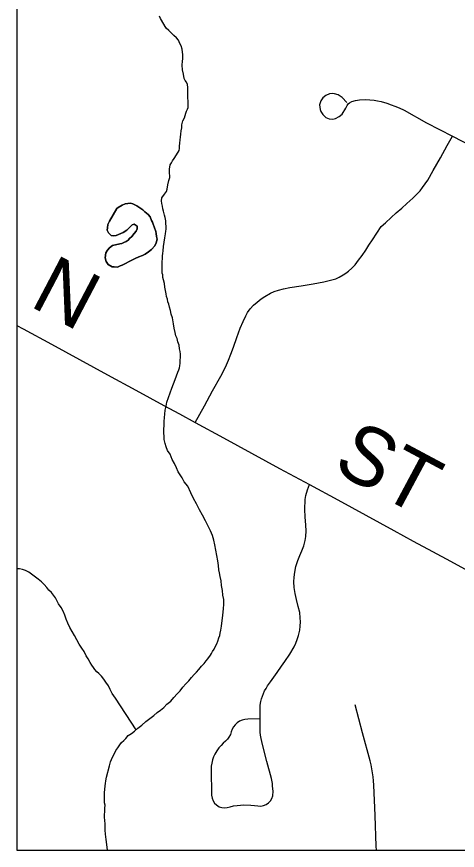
# Model space of a CAD drawing. Extents: x 103424 to 286016, y 38711 to 110967.
# Drawn here: x 103424 to 105694, y 38711 to 43011 of the extents above; entities that cross this region are included whole.
import ezdxf

# ---------------------------------------------------------------- set-up
doc = ezdxf.new("R2010")
doc.units = 0
for name, color, linetype in [('GM_X_Corporation', 7, 'Continuous'), ('GM_X_County_Road', 7, 'Continuous'), ('GM_X_County_Road_Text', 7, 'Continuous'), ('GM_X_Minor_Lake', 7, 'Continuous'), ('GM_X_Minor_River', 7, 'Continuous'), ('GM_X_Township_Road', 7, 'Continuous')]:
    doc.layers.add(name, color=color, linetype=linetype)

msp = doc.modelspace()

# ---------------------------------------------------------------- linework, layer by layer
at = {"layer": 'GM_X_Corporation'}
for points in [[(103423.7, 96534.8), (103423.7, 38711.2), (175679.7, 38711.2), (175679.7, 110967.2), (119699, 110967.2), (119716.9, 106542.5), (119719.8, 106322.8), (119720.8, 106006.3), (119709.7, 99445.7), (119706.4, 99064.2), (119663.9, 96690), (117026.4, 96688.2), (115542.1, 96665), (105081.7, 96574.5)], [(103423.7, 43132.7), (103423.7, 38711.2), (119963.5, 38711.2), (119934.2, 43543), (116952, 43470.9), (108691.3, 43264.4)]]:
    msp.add_lwpolyline(points, close=True, dxfattribs=at)
at = {"layer": 'GM_X_County_Road'}
msp.add_lwpolyline([(103423.7, 41418.7), (103457.3, 41400.5), (103602.3, 41321.6), (103747.3, 41242.7), (103892.3, 41163.9), (104037.3, 41085), (104182.3, 41006.1), (104263.1, 40962.2), (104343.9, 40918.3), (104488.9, 40839.3), (104633.8, 40760.4), (104778.8, 40681.4), (104855.9, 40639.4), (104933, 40597.4), (105077.9, 40518.4), (105222.9, 40439.5), (105367.8, 40360.5), (105467.1, 40306.4), (105566.5, 40252.2), (105658.5, 40202.8), (105750.4, 40153.3)], dxfattribs=at)
at = {"layer": 'GM_X_Minor_Lake'}
for points in [[(103939.2, 42021.1), (103946.5, 42026.4), (103966.4, 42038.9), (103982.5, 42045.2), (103996.6, 42047.4), (104010.7, 42049.7), (104022.8, 42045.9), (104033, 42040), (104043.2, 42036.1), (104063.6, 42022.3), (104073.8, 42014.4), (104084.1, 42004.4), (104100.4, 41990.6), (104110.7, 41978.6), (104119.1, 41960.6), (104123.3, 41950.5), (104127.5, 41940.5), (104131.8, 41926.4), (104140.3, 41902.3), (104142.4, 41892.3), (104144.7, 41878.1), (104147, 41864), (104143.3, 41843.8), (104135.4, 41829.5), (104117.6, 41811), (104103.7, 41798.7), (104085.7, 41786.3), (104071.7, 41780), (104053.7, 41771.6), (104033.6, 41763.2), (104003.6, 41748.6), (103983.6, 41738.1), (103967.6, 41729.8), (103957.6, 41725.6), (103943.6, 41719.3), (103925.4, 41721), (103915.3, 41720.8), (103894.9, 41732.6), (103884.6, 41748.6), (103880.2, 41766.7), (103883.8, 41793.1), (103891.6, 41807.3), (103901.5, 41819.6), (103917.5, 41830), (103955.7, 41838.7), (103965.7, 41840.9), (103975.7, 41847.1), (103987.8, 41851.3), (103997.7, 41857.6), (104005.7, 41867.8), (104017.6, 41878.1), (104029.4, 41892.4), (104039.3, 41904.7), (104045.2, 41916.9), (104044.9, 41931.1), (104028.6, 41940.9), (104018.6, 41936.7), (104004.7, 41924.3), (103990.8, 41910), (103972.9, 41897.5), (103948.8, 41887.1), (103936.8, 41882.8), (103924.7, 41880.6), (103910.6, 41882.4), (103896.2, 41896.3), (103889.9, 41910.3), (103891.7, 41922.5), (103893.5, 41938.7), (103901.2, 41957), (103939.2, 42021.1)], [(103939.2, 42021.1), (103901.2, 41957), (103893.5, 41938.7), (103891.7, 41922.5), (103889.9, 41910.3), (103896.2, 41896.3), (103910.6, 41882.4), (103924.7, 41880.6), (103936.8, 41882.8), (103948.8, 41887.1), (103972.9, 41897.5), (103990.8, 41910), (104004.7, 41924.3), (104018.6, 41936.7), (104028.6, 41940.9), (104044.9, 41931.1), (104045.2, 41916.9), (104039.3, 41904.7), (104029.4, 41892.4), (104017.6, 41878.1), (104005.7, 41867.8), (103997.7, 41857.6), (103987.8, 41851.3), (103975.7, 41847.1), (103965.7, 41840.9), (103955.7, 41838.7), (103917.5, 41830), (103901.5, 41819.6), (103891.6, 41807.3), (103883.8, 41793.1), (103880.2, 41766.7), (103884.6, 41748.6), (103894.9, 41732.6), (103915.3, 41720.8), (103925.4, 41721), (103943.6, 41719.3)], [(103943.6, 41719.3), (103957.6, 41725.6), (103967.6, 41729.8), (103983.6, 41738.1), (104003.6, 41748.6), (104033.6, 41763.2), (104053.7, 41771.6), (104071.7, 41780), (104085.7, 41786.3), (104103.7, 41798.7), (104117.6, 41811), (104135.4, 41829.5), (104143.3, 41843.8), (104147, 41864), (104144.7, 41878.1), (104142.4, 41892.3), (104140.3, 41902.3), (104131.8, 41926.4), (104127.5, 41940.5), (104123.3, 41950.5), (104119.1, 41960.6), (104110.7, 41978.6), (104100.4, 41990.6), (104084.1, 42004.4), (104073.8, 42014.4), (104063.6, 42022.3), (104043.2, 42036.1), (104033, 42040), (104022.8, 42045.9), (104010.7, 42049.7), (103996.6, 42047.4), (103982.5, 42045.2), (103966.4, 42038.9), (103946.5, 42026.4), (103939.2, 42021.1)]]:
    msp.add_lwpolyline(points, dxfattribs=at)
at = {"layer": 'GM_X_Minor_River'}
for points in [[(104277.6, 42736.9), (104277.2, 42761.2), (104278.8, 42781.4), (104280.7, 42793.6), (104280.5, 42805.7), (104280.3, 42815.8), (104278.1, 42827.9), (104275.8, 42844), (104271.5, 42860.1), (104265.2, 42872.1), (104256.8, 42890.1), (104246.6, 42902.1), (104234.2, 42914), (104219.9, 42927.9), (104207.6, 42939.8), (104193.3, 42951.7), (104164.2, 43001.7), (104159.9, 43013.8)], [(104247.6, 41158.6), (104253.4, 41176.9), (104259.2, 41189.1), (104263.1, 41199.3), (104264.9, 41209.4), (104266.7, 41223.6), (104266.5, 41235.7), (104268.2, 41255.9), (104267.9, 41270), (104265.7, 41284.2), (104263.4, 41298.3), (104261.1, 41316.4), (104254.7, 41334.5), (104250.4, 41350.6), (104244.1, 41364.6), (104239.8, 41382.7), (104235.4, 41404.9), (104231, 41427), (104226.4, 41457.2), (104220.1, 41477.4), (104215.7, 41495.5), (104211.4, 41513.6), (104207.1, 41527.6), (104202.9, 41539.7), (104200.6, 41553.8), (104196.3, 41567.9), (104194.1, 41582), (104189.8, 41598.1), (104187.5, 41616.2), (104185.1, 41634.4), (104180.8, 41654.5), (104176.5, 41666.5), (104176.3, 41678.7), (104174.1, 41688.7), (104173.9, 41702.9), (104173.6, 41723.1), (104173.1, 41747.3), (104174.9, 41763.5), (104174.6, 41777.6), (104176.5, 41789.8), (104178.2, 41803.9), (104179.9, 41826.2), (104183.6, 41848.5), (104187.2, 41870.8), (104190.9, 41891), (104192.7, 41905.2), (104194.5, 41915.3), (104191.8, 41957.7), (104189.5, 41975.9), (104185.2, 41987.9), (104180.9, 42008), (104176.6, 42020.1), (104174.4, 42034.2), (104172.1, 42048.3), (104169.9, 42060.4), (104171.6, 42076.6), (104185.5, 42095), (104195.3, 42109.3), (104199.1, 42121.5), (104202.8, 42143.8), (104208.5, 42166.1), (104212.2, 42182.3), (104212.1, 42192.4), (104211.9, 42202.5), (104211.7, 42212.6), (104211.5, 42224.7), (104215.2, 42247), (104221.1, 42257.2), (104227, 42267.4), (104234.8, 42279.6), (104246.6, 42298), (104260.4, 42320.5), (104262.2, 42330.6), (104262, 42342.7), (104263.8, 42358.9), (104265.5, 42375.1), (104267.3, 42389.3), (104269, 42405.5), (104270.8, 42421.7), (104274.5, 42437.9), (104274.3, 42454), (104280, 42474.3), (104287.8, 42488.6), (104291.6, 42500.8), (104295.5, 42513), (104299.3, 42523.1), (104303.2, 42533.3), (104307.1, 42543.5), (104306.9, 42553.6), (104306.7, 42563.7), (104306.5, 42575.8), (104306.3, 42591.9), (104306, 42610.1), (104305.6, 42628.3), (104305.3, 42646.5), (104303.1, 42660.6), (104298.8, 42672.6), (104292.6, 42682.6), (104286.4, 42692.6), (104284, 42714.8), (104277.6, 42736.9)], [(103917.4, 39191.4), (103927.2, 39209.8), (103935, 39226.1), (103944.8, 39240.4), (103954.7, 39254.7), (103964.6, 39267), (103976.5, 39277.3), (103986.4, 39287.5), (103998.3, 39303.9), (104016.2, 39314.3), (104030.2, 39326.6), (104048.1, 39341.1), (104068, 39357.6), (104089.9, 39376.1), (104109.8, 39390.6), (104129.7, 39407.1), (104147.6, 39421.5), (104165.6, 39433.9), (104181.5, 39448.3), (104197.4, 39464.8), (104217.3, 39481.2), (104233.1, 39499.7), (104250.9, 39518.2), (104266.8, 39534.6), (104280.6, 39553), (104294.5, 39569.4), (104310.3, 39585.8), (104324.2, 39602.2), (104338, 39618.6), (104349.9, 39630.9), (104361.8, 39643.2), (104375.7, 39661.6), (104389.6, 39674), (104399.4, 39688.3), (104409.3, 39698.6), (104423.2, 39717), (104427, 39727.1), (104432.9, 39737.3), (104440.8, 39749.6), (104448.6, 39763.8), (104454.5, 39776.1), (104460.3, 39790.3), (104466, 39806.6), (104469.9, 39818.7), (104471.7, 39830.9), (104475.5, 39847.1), (104479.2, 39867.4), (104486.3, 39924.1), (104488, 39940.3), (104489.7, 39958.5), (104491.4, 39978.7), (104491, 40005), (104486.6, 40027.1), (104484.1, 40051.3), (104479.7, 40077.5), (104477.2, 40101.7), (104472.8, 40123.9), (104468.5, 40142), (104466.2, 40158.1), (104463.8, 40180.3), (104459.4, 40204.4), (104454.9, 40232.7), (104450.4, 40258.9), (104443.9, 40287), (104439.4, 40311.2), (104433, 40335.3), (104422.5, 40359.4), (104410, 40383.4), (104397.4, 40411.5), (104380.8, 40439.5), (104366.2, 40467.6), (104349.5, 40497.6), (104334.9, 40525.7), (104320.3, 40555.7), (104305.6, 40589.8), (104287.1, 40611.7), (104276.6, 40631.8), (104266.3, 40647.8), (104255.9, 40663.8), (104247.5, 40683.8), (104237, 40705.9), (104224.6, 40727.9), (104214, 40754), (104201.6, 40774), (104193.2, 40792), (104188.9, 40810.1), (104184.5, 40830.3), (104184.2, 40846.4), (104181.9, 40864.6), (104181.6, 40882.8), (104183.3, 40903), (104183, 40923.2), (104184.6, 40943.4), (104186.3, 40961.6), (104188, 40981.8), (104193.7, 41002.1), (104197.4, 41022.4), (104222.4, 41095.6), (104232.1, 41117.9), (104239.8, 41140.3), (104247.6, 41158.6)], [(104038.6, 39333.4), (103932.5, 39496.8), (103915.9, 39520.7), (103905.5, 39540.8), (103897.1, 39558.8), (103882.7, 39578.8), (103872.3, 39594.8), (103860, 39608.7), (103847.6, 39622.6), (103837.4, 39632.6), (103827.1, 39644.5), (103818.8, 39654.5), (103810.6, 39666.5), (103802.2, 39680.5), (103791.9, 39698.5), (103781.5, 39714.5), (103771, 39736.5), (103758.6, 39754.5), (103746.2, 39774.5), (103733.7, 39796.6), (103721.2, 39818.6), (103708.8, 39840.6), (103698.3, 39860.6), (103687.9, 39882.7), (103679.5, 39902.7), (103671, 39924.8), (103662.6, 39944.9), (103652.2, 39962.9), (103639.8, 39982.9), (103631.5, 39996.9), (103623.1, 40012.9), (103612.8, 40026.9), (103602.5, 40040.9), (103590.2, 40052.8), (103579.9, 40066.8), (103565.5, 40082.7), (103551.1, 40096.6), (103534.7, 40110.5), (103520.4, 40120.3), (103485.7, 40146), (103469.4, 40153.8), (103453.2, 40159.6), (103439, 40163.4), (103424.9, 40163.2), (103423.7, 40163.2)], [(103891.2, 38711.2), (103891.2, 38712.2), (103888.7, 38740.4), (103884.2, 38766.6), (103881.7, 38794.9), (103879.3, 38815), (103879.1, 38831.2), (103878.8, 38847.4), (103878.5, 38865.5), (103876.2, 38881.7), (103876, 38895.8), (103877.7, 38910), (103877.4, 38928.1), (103879.2, 38944.3), (103877, 38956.4), (103876.7, 38972.6), (103876.5, 38984.7), (103876.2, 38998.8), (103876.1, 39008.9), (103877.8, 39025.1), (103879.5, 39043.4), (103881.4, 39055.5), (103883.1, 39069.7), (103886.9, 39087.9), (103902, 39146.7), (103907.7, 39167), (103917.4, 39191.4)]]:
    msp.add_lwpolyline(points, dxfattribs=at)
at = {"layer": 'GM_X_Township_Road'}
for points in [[(105124.6, 42569.1), (105100.2, 42594.8), (105080.8, 42607.4), (105060.7, 42613.4), (105049.1, 42614.4), (105036.2, 42612.6), (105016.5, 42604.7), (105001.1, 42592.5), (104990.9, 42576.2), (104983.3, 42556.8), (104986.7, 42533.1), (104990.9, 42522.2), (105001.4, 42506.2), (105016, 42491.2), (105033.6, 42484.5), (105052.1, 42481.9), (105067.4, 42486), (105084.8, 42495.8), (105100.2, 42509.1), (105120.3, 42538.9), (105126.7, 42553.6), (105132.5, 42561.6), (105138, 42566.6), (105151.5, 42573.5), (105169.4, 42578.9), (105190.2, 42581.9), (105220, 42583.1), (105243.3, 42582.5), (105265.9, 42580.1), (105283.2, 42577.1), (105302.2, 42572.9), (105331.6, 42564.3), (105352.9, 42556.9), (105373, 42550.1), (105394.6, 42540.7), (105420.2, 42528.9), (105535, 42464.2), (105668.9, 42394.5), (105815.6, 42318.9)], [(104343.9, 40918.3), (104391.4, 41004.6), (104433.2, 41080.6), (104475.1, 41156.7), (104490.4, 41186.5), (104504.7, 41215.4), (104514.9, 41238.6), (104527.9, 41270), (104540.9, 41306), (104557.7, 41355.7), (104576.1, 41404.7), (104590.6, 41438.9), (104603.7, 41467.5), (104613.6, 41485.9), (104626.7, 41503.5), (104644.3, 41522.7), (104662.7, 41538.7), (104684.1, 41555.6), (104702.5, 41567.1), (104731.6, 41584.7), (104749.9, 41593.1), (104772.1, 41600.8), (104798.9, 41607.6), (104831.1, 41613.8), (104890.2, 41622.7), (104950.8, 41632.7), (105007.2, 41643.6), (105047.8, 41653.6), (105067.7, 41659.7), (105086, 41668.1), (105106, 41678.8), (105120.2, 41688.5), (105133.8, 41699.2), (105150.4, 41713.3), (105168, 41731.7), (105185, 41754.5), (105203.9, 41779.9), (105222, 41807.4), (105238, 41831.8), (105256.4, 41859.8), (105278.9, 41894.1), (105302.7, 41928.5), (105323.8, 41948.6), (105353.1, 41974.6), (105379.3, 41998.9), (105407.5, 42022.9), (105434.9, 42047.3), (105465.8, 42074.7), (105487.5, 42097.4), (105502, 42112.7), (105515.6, 42129.8), (105529.1, 42148.4), (105542.4, 42168.1), (105570, 42217.5), (105606.8, 42283.3), (105642.2, 42346.7), (105668.9, 42394.5)], [(104677.8, 39388.9), (104614.6, 39388.5), (104598.5, 39386.8), (104584.9, 39383), (104572.3, 39377.3), (104559.5, 39368.7), (104549.4, 39359.1), (104541.1, 39348), (104534.3, 39335.8), (104529.5, 39322.3), (104524.7, 39309.4), (104517.4, 39295.5), (104509.3, 39284.3), (104500.3, 39274.1), (104488.4, 39263.8), (104476.6, 39252.5), (104466, 39240.3), (104454.7, 39224.5), (104444.9, 39207.5), (104438.3, 39192.7), (104433, 39177.3), (104429, 39161.6), (104426.5, 39145.5), (104425.2, 39129.3), (104428.2, 38995.7), (104430.4, 38979.6), (104435.7, 38966.7), (104443.3, 38955), (104453.1, 38945.3), (104467.9, 38936.3), (104481.2, 38932.2), (104495.1, 38930.8), (104508.9, 38932.3), (104523.8, 38936.2), (104541.4, 38939.9), (104559.1, 38942.7), (104576.9, 38944.5), (104594.8, 38945.5), (104630.5, 38944.5), (104648.4, 38942.6), (104665.8, 38939.9), (104681.9, 38939.3), (104696.2, 38942.1), (104709.8, 38947.7), (104721.2, 38955.3), (104731.5, 38965.8), (104739.3, 38978.2), (104744.3, 38992.1), (104745.2, 39017), (104742.6, 39042), (104741.1, 39056), (104736.1, 39081), (104713.4, 39168.8), (104690.6, 39256.6), (104686.3, 39272.5), (104683.1, 39288.5), (104680.8, 39304.6), (104679, 39320.9), (104678.3, 39339.8), (104677.8, 39388.9), (104678.8, 39459.8), (104681.9, 39478.1), (104685.1, 39492.5), (104689.7, 39506.5), (104695, 39520.3), (104701.5, 39533.5), (104708.6, 39546.4), (104716.9, 39558.9), (104732.3, 39580.9), (104765.2, 39628), (104788.5, 39661.3), (104805.2, 39685.2), (104831.9, 39723.4), (104853.9, 39760.6), (104862.4, 39779.7), (104869.8, 39798.7), (104876, 39820.1), (104881.9, 39846.3), (104884.1, 39867.6), (104885.4, 39889.4), (104884.8, 39910.6), (104883, 39937.2), (104874.9, 39969.5), (104866.1, 40004.9), (104858.5, 40035.8), (104853.8, 40067.4), (104852.6, 40096.1), (104853.8, 40120.8), (104857.2, 40145.5), (104862.4, 40174.4), (104872.9, 40205.9), (104882.9, 40231.2), (104892.8, 40256.3), (104902.6, 40282.2), (104910.1, 40308.6), (104914.1, 40329.2), (104915.2, 40359.1), (104913.5, 40387.8), (104910.1, 40432), (104907.7, 40469.4), (104910.1, 40521), (104912.9, 40541.1), (104921.5, 40571), (104933, 40597.4)], [(105277.2, 38711.2), (105276.3, 38733.4), (105270.1, 38890.6), (105263.9, 39047.7), (105262.6, 39068.9), (105260.6, 39090.1), (105257.9, 39111.2), (105254.1, 39132.2), (105249.8, 39153), (105244.8, 39173.6), (105206.2, 39318), (105167.7, 39462.4)]]:
    msp.add_lwpolyline(points, dxfattribs=at)

# ---------------------------------------------------------------- texts
at = {"layer": 'GM_X_County_Road_Text'}
for s, height, rotation, p in [('N', 301.9, 332.3569, (103483.7, 41521.8)), ('ST', 301.87, 331.8603, (105043.9, 40674.1))]:
    msp.add_text(s, height=height, rotation=rotation, dxfattribs=at).set_placement(p)

doc.saveas('drawing.dxf')
